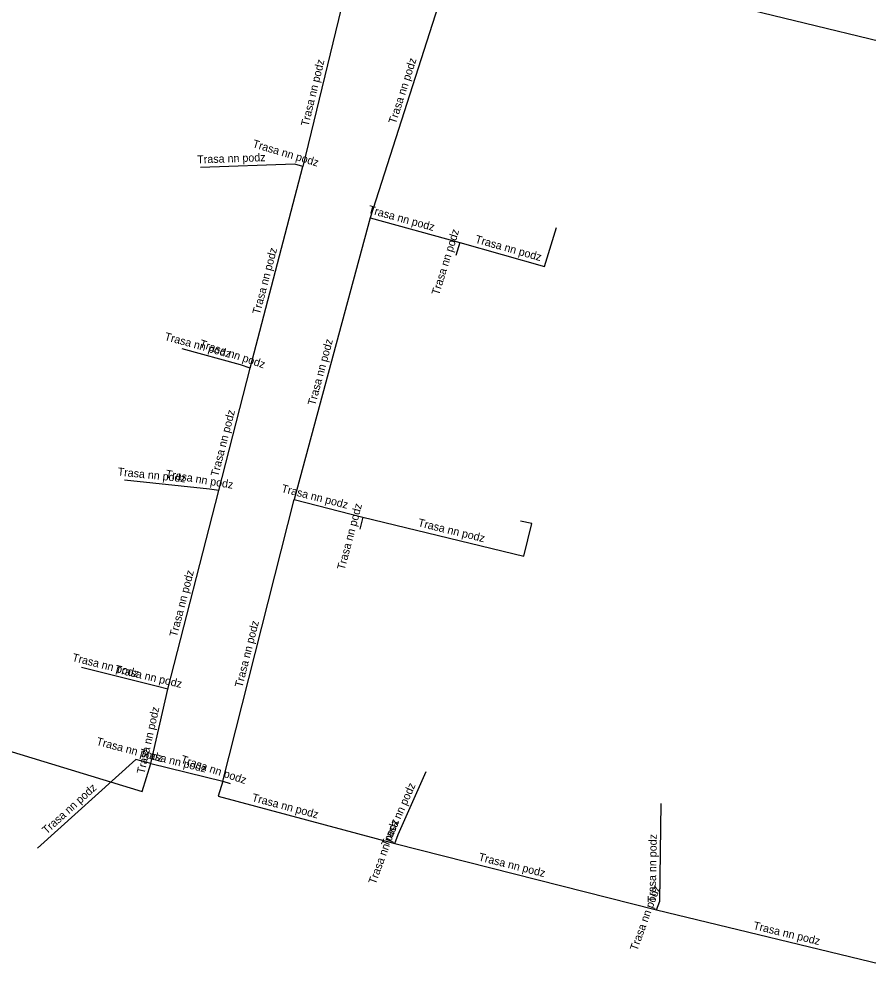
# Model space of a CAD drawing. Extents: x -737281 to -735046, y -1033441 to -1031241.
# Drawn here: x -735834.5 to -735728.3, y -1032077.7 to -1031957.7 of the extents above; entities that cross this region are included whole.
import ezdxf

# ---------------------------------------------------------------- set-up
doc = ezdxf.new("R2010")
doc.units = 0
doc.layers.add('Level 11', color=7, linetype='Continuous')
doc.layers.add('Level 20', color=7, linetype='Continuous')

msp = doc.modelspace()

# ---------------------------------------------------------------- linework, layer by layer
at = {"layer": 'Level 11'}
for p, q in [((-735779.4, -1031947.5), (-735790.6, -1031982.5)), ((-735721.4, -1031961.8), (-735769.1, -1031950.2)), ((-735793.7, -1031954.2), (-735799, -1031976.1)), ((-735800, -1031975.8), (-735811.8, -1031976.2)), ((-735805.6, -1032001.3), (-735799, -1031976.1)), ((-735799, -1031976.1), (-735800, -1031975.8)), ((-735790.6, -1031982.5), (-735800.1, -1032017.7)), ((-735790.6, -1031982.5), (-735779.4, -1031985.6)), ((-735779.4, -1031985.6), (-735779.9, -1031987.2)), ((-735806.8, -1032000.9), (-735814.1, -1031998.9)), ((-735809.5, -1032016.6), (-735805.6, -1032001.3)), ((-735805.6, -1032001.3), (-735806.8, -1032000.9)), ((-735810.7, -1032016.4), (-735821.3, -1032015.3)), ((-735815.9, -1032041.4), (-735809.5, -1032016.6)), ((-735809.5, -1032016.6), (-735810.7, -1032016.4)), ((-735809, -1032052.9), (-735800.1, -1032017.7)), ((-735800.1, -1032017.7), (-735791.5, -1032019.9)), ((-735791.5, -1032019.9), (-735791.9, -1032021.4)), ((-735817.2, -1032041.1), (-735826.7, -1032038.7)), ((-735815.9, -1032041.4), (-735817.2, -1032041.1)), ((-735818, -1032050.7), (-735815.9, -1032041.4)), ((-735819.9, -1032050.2), (-735832.2, -1032061.3)), ((-735818, -1032050.7), (-735819.9, -1032050.2)), ((-735818, -1032050.7), (-735809, -1032052.9)), ((-735787.1, -1032059.6), (-735783.6, -1032051.7)), ((-735809, -1032052.9), (-735808.1, -1032053.2)), ((-735754.4, -1032067.9), (-735754.2, -1032055.7)), ((-735787.5, -1032060.7), (-735787.1, -1032059.6)), ((-735787.5, -1032060.7), (-735754.8, -1032069)), ((-735754.8, -1032069), (-735754.4, -1032067.9)), ((-735754.8, -1032069), (-735718.77, -1032077.74))]:
    msp.add_line(p, q, dxfattribs=at)
for points in [[(-735779.4, -1031985.6), (-735768.8, -1031988.6), (-735767.3, -1031983.7)], [(-735791.5, -1032019.9), (-735771.4, -1032024.8), (-735770.4, -1032020.7), (-735771.8, -1032020.4)], [(-735860.5, -1032041.6), (-735819.1, -1032054.2), (-735818, -1032050.7)], [(-735809, -1032052.9), (-735809.6, -1032054.8), (-735787.5, -1032060.7)]]:
    msp.add_lwpolyline(points, dxfattribs=at)

# ---------------------------------------------------------------- texts
at = {"layer": 'Level 20'}
for rotation, p in [(76.3955, (-735798.31, -1031971.14)), (72.2553, (-735787.39, -1031970.84)), (343.3008, (-735805.38, -1031973.66)), (1.9415, (-735812.2, -1031975.71)), (344.5287, (-735790.93, -1031981.89)), (72.646, (-735782, -1031992.25)), (344.1975, (-735777.55, -1031985.6)), (75.3236, (-735804.38, -1031994.65)), (344.6785, (-735816.38, -1031997.76)), (341.5651, (-735812.01, -1031998.64)), (74.8965, (-735797.47, -1032006.04)), (75.6997, (-735809.59, -1032014.92)), (354.0754, (-735822.2, -1032014.7)), (350.5377, (-735816.22, -1032014.97)), (345.6507, (-735801.77, -1032016.76)), (75.0686, (-735793.8, -1032026.6)), (346.2996, (-735784.69, -1032021.04)), (75.5297, (-735814.75, -1032034.96)), (75.8107, (-735806.58, -1032041.27)), (345.8219, (-735827.92, -1032037.88)), (347.0054, (-735822.56, -1032039.35)), (77.2756, (-735818.82, -1032052.07)), (345.2564, (-735824.9, -1032048.37)), (346.2637, (-735819.49, -1032049.82)), (341.5651, (-735814.36, -1032050.59)), (66.1048, (-735788.35, -1032061.2)), (42.0643, (-735831.05, -1032059.59)), (345.0524, (-735805.46, -1032055.39)), (70.0169, (-735789.92, -1032065.89)), (89.0608, (-735754.9, -1032068.08)), (345.7578, (-735777.12, -1032062.82)), (70.0169, (-735757.22, -1032074.19)), (346.3619, (-735742.78, -1032071.4))]:
    msp.add_text('Trasa nn podz', height=1, rotation=rotation, dxfattribs=at).set_placement(p)

doc.saveas('drawing.dxf')
